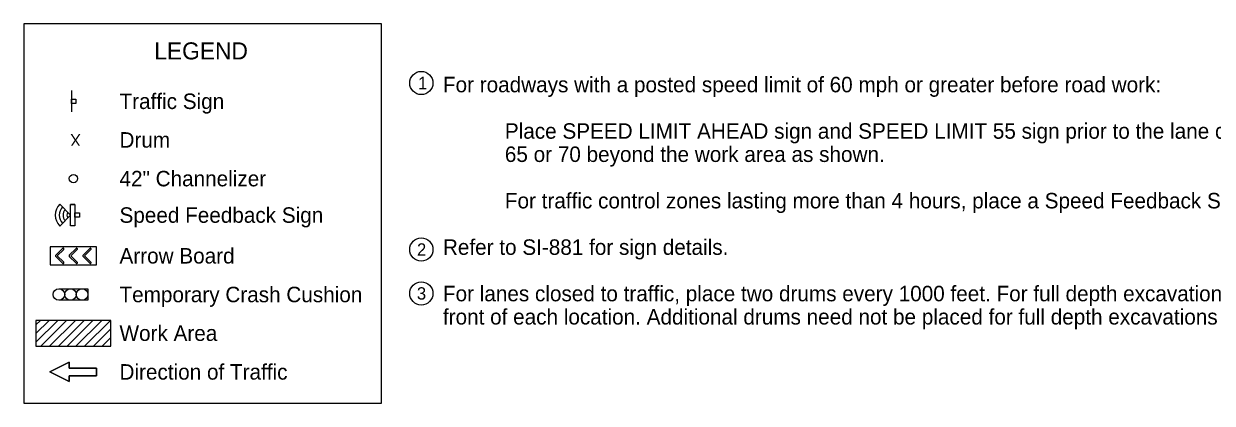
# Model space of a CAD drawing. Extents: x 10133 to 2270741, y 5363 to 1733450.
# Drawn here: x 28197 to 29731, y 5397 to 5888 of the extents above; entities that cross this region are included whole.
import ezdxf

# ---------------------------------------------------------------- set-up
doc = ezdxf.new("R2010")
doc.units = 0
for name, color, linetype in [('dsnNonPlotable', 7, 'Continuous'), ('dsnShtPlotShapeBatchPrint', 7, 'Continuous'), ('dsnStdBlockModified', 7, 'Continuous'), ('dsnStdBorder', 7, 'Continuous'), ('dsnStdTable', 7, 'Continuous')]:
    doc.layers.add(name, color=color, linetype=linetype)

msp = doc.modelspace()

# ---------------------------------------------------------------- linework, layer by layer
at = {"layer": 'dsnNonPlotable'}
msp.add_lwpolyline([(28196.6, 5887.6), (28196.6, 5397.4), (28658.4, 5397.4), (28658.4, 5887.6), (28196.6, 5887.6)], dxfattribs=at)
at = {"layer": 'dsnShtPlotShapeBatchPrint'}
for centre in [(28710, 5811.1), (28710, 5596), (28710, 5539.3)]:
    msp.add_circle(centre, 15, dxfattribs=at)
at = {"layer": 'dsnStdBlockModified'}
for p, q in [((28243, 5654.6), (28257.1, 5640.5)), ((28262.7, 5654.2), (28257.1, 5654.2)), ((28257.1, 5640.5), (28243, 5626.3)), ((28262.7, 5626.7), (28257.1, 5626.7))]:
    msp.add_line(p, q, dxfattribs=at)
for radius, start, end in [(20.3, 135.88, 224.0313), (15.3, 136.1665, 223.7159), (10.3, 136.7294, 223.0963), (5.32, 138.7005, 221.2995)]:
    msp.add_arc((28257.6, 5640.4), radius, start, end, dxfattribs=at)
at = {"layer": 'dsnStdBorder'}
for p, q in [((28258, 5801.3), (28258, 5773.8)), ((28262.7, 5654.2), (28262.7, 5626.7)), ((28237.9, 5588.6), (28246.7, 5597.4)), ((28255.4, 5588.6), (28264.2, 5597.4)), ((28273.1, 5588.6), (28281.9, 5597.4)), ((28241.9, 5545.4), (28279.4, 5545.4)), ((28279.4, 5545.4), (28279.4, 5530.4)), ((28279.4, 5530.4), (28241.9, 5530.4)), ((28212.3, 5498.9), (28218, 5504.5)), ((28212.3, 5487.6), (28229.3, 5504.5)), ((28212.3, 5476.2), (28240.6, 5504.5)), ((28218.6, 5471.2), (28251.9, 5504.5)), ((28229.9, 5471.2), (28263.2, 5504.5)), ((28241.3, 5471.2), (28274.5, 5504.5)), ((28252.6, 5471.2), (28285.9, 5504.5)), ((28263.9, 5471.2), (28297.2, 5504.5)), ((28275.2, 5471.2), (28308.5, 5504.5)), ((28286.5, 5471.2), (28309, 5493.7)), ((28297.8, 5471.2), (28309, 5482.4))]:
    msp.add_line(p, q, dxfattribs=at)
for points in [[(28258.1, 5784.8), (28258.1, 5790.4), (28263.7, 5790.4), (28263.7, 5784.8)], [(28257.1, 5626.7), (28257.1, 5654.2), (28262.7, 5654.2), (28262.7, 5626.7)], [(28262.7, 5637.8), (28262.7, 5643.4), (28268.4, 5643.4), (28268.4, 5637.8)], [(28290.7, 5599.3), (28230.7, 5599.3), (28230.7, 5576.4), (28290.7, 5576.4)], [(28212.3, 5504.5), (28212.3, 5471.2), (28309, 5471.2), (28309, 5504.5)], [(28290.3, 5442.9), (28290.3, 5432.9), (28255.3, 5432.9), (28255.3, 5425.4), (28230.3, 5437.9), (28255.3, 5450.4), (28255.3, 5442.9)]]:
    msp.add_lwpolyline(points, close=True, dxfattribs=at)
for points in [[(28246.7, 5578.3), (28246.7, 5578.3), (28237.9, 5587.1), (28237.9, 5587.1)], [(28248.1, 5596), (28248.1, 5595.9), (28239.6, 5587.9), (28248.1, 5579.8)], [(28264.2, 5578.3), (28264.2, 5578.3), (28255.4, 5587.1), (28255.4, 5587.1)], [(28265.7, 5596), (28265.6, 5595.9), (28257.2, 5587.9), (28265.7, 5579.8)], [(28281.9, 5578.3), (28281.9, 5578.3), (28273.1, 5587.1), (28273, 5587.1)], [(28283.3, 5596), (28283.3, 5595.9), (28274.8, 5587.9), (28283.3, 5579.8)], [(28255.3, 5442.9), (28255.3, 5450.4), (28230.3, 5437.9), (28255.3, 5425.4), (28255.3, 5432.9), (28290.3, 5432.9), (28290.3, 5442.9), (28255.3, 5442.9)]]:
    msp.add_lwpolyline(points, dxfattribs=at)
for centre, radius in [((28260.7, 5687.6), 5.37), ((28260.7, 5687.6), 5.37), ((28241.9, 5537.9), 7.5), ((28241.9, 5537.9), 7.5), ((28256.9, 5537.9), 7.5), ((28256.9, 5537.9), 7.5), ((28271.9, 5537.9), 7.5), ((28271.9, 5537.9), 7.5)]:
    msp.add_circle(centre, radius, dxfattribs=at)
for centre, start, end in [((28238.6, 5587.9), 134.1616, 224.6098), ((28247.4, 5596.7), 315.0975, 135.281), ((28256.1, 5587.9), 134.1616, 224.6098), ((28265, 5596.7), 315.0975, 135.281), ((28273.8, 5587.9), 134.1616, 224.6098), ((28282.6, 5596.7), 315.0975, 135.281), ((28247.4, 5579), 226.201, 47.3602), ((28265, 5579), 226.201, 47.3602), ((28282.6, 5579), 226.201, 47.3602)]:
    msp.add_arc(centre, 1.03, start, end, dxfattribs=at)

# ---------------------------------------------------------------- texts
at = {"layer": 'dsnShtPlotShapeBatchPrint'}
for s, p in [('1', (28705.8, 5803.1)), ('2', (28704.4, 5588)), ('3', (28704.3, 5531.3))]:
    msp.add_text(s, height=16, dxfattribs=at).set_placement(p)
at = {"layer": 'dsnStdBorder'}
for s, height, p in [('LEGEND', 22, (28365.1, 5841.6)), ('Traffic Sign', 20, (28320.2, 5777.5)), ('Drum', 20, (28320.2, 5727.6)), ('42" Channelizer ', 20, (28320.2, 5677.6)), ('Speed Feedback Sign', 20, (28320.2, 5630.5)), ('Arrow Board', 20, (28320.2, 5577.9)), ('Temporary Crash Cushion', 20, (28320.2, 5527.9)), ('Work Area', 20, (28320.2, 5477.9)), ('Direction of Traffic', 20, (28320.2, 5427.9))]:
    msp.add_text(s, height=height, dxfattribs=at).set_placement(p)
msp.add_text('X', height=15, rotation=180, dxfattribs=at).set_placement((28270.1, 5745.1))
at = {"layer": 'dsnStdTable'}
for s, p in [('For roadways with a posted speed limit of 60 mph or greater before road work:', (28737.9, 5799.1)), ('Place SPEED LIMIT AHEAD sign and SPEED LIMIT 55 sign prior to the lane closure as shown. Place SPEED LIMIT', (28817.9, 5739.1)), ('65 or 70 beyond the work area as shown.', (28817.9, 5709.1)), ('For traffic control zones lasting more than 4 hours, place a Speed Feedback Sign at the end of the merge taper.', (28817.9, 5649.1)), ('Refer to SI-881 for sign details.', (28737.9, 5589.1)), ('For lanes closed to traffic, place two drums every 1000 feet. For full depth excavations in a closed lane, place two drums in ', (28737.9, 5529.1)), ('front of each location. Additional drums need not be placed for full depth excavations spaced closer than 150 feet.', (28737.9, 5499.1))]:
    msp.add_text(s, height=20, dxfattribs=at).set_placement(p)

doc.saveas('drawing.dxf')
